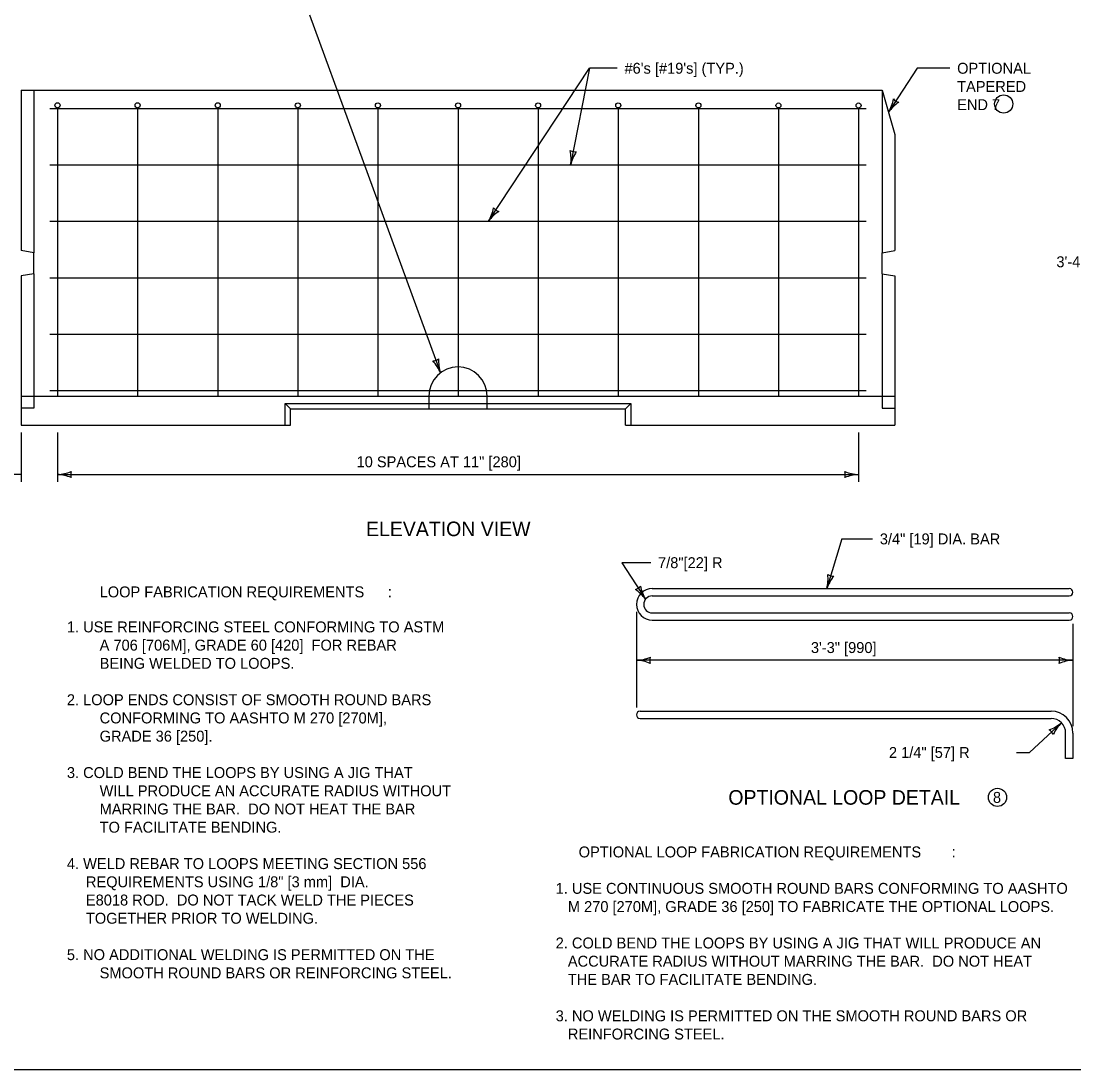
# Model space of a CAD drawing. Extents: x 49991.4 to 50021, y 49987.6 to 50011.4.
# Drawn here: x 50003.08 to 50008.86, y 49987.8 to 49993.56 of the extents above; entities that cross this region are included whole.
import ezdxf

# ---------------------------------------------------------------- set-up
doc = ezdxf.new("R2010")
doc.units = 0
for name, color, linetype in [('Level 1', 7, 'Continuous'), ('Level 2', 7, 'Continuous'), ('Level 3', 7, 'Continuous'), ('Level 4', 7, 'Continuous')]:
    doc.layers.add(name, color=color, linetype=linetype)

msp = doc.modelspace()

# ---------------------------------------------------------------- linework, layer by layer
at = {"layer": 'Level 1'}
for p, q in [((50003.0765, 49993.1796), (50007.8063, 49993.1796)), ((50003.0765, 49993.1796), (50003.0766, 49992.2998)), ((50007.8063, 49993.1796), (50007.8765, 49992.9369)), ((50003.2341, 49993.0799), (50007.7191, 49993.0799)), ((50003.2766, 49993.0817), (50003.2766, 49991.4996)), ((50003.7166, 49993.0817), (50003.7166, 49991.4996)), ((50004.1566, 49993.0817), (50004.1566, 49991.4996)), ((50004.5966, 49993.0817), (50004.5966, 49991.4996)), ((50005.0366, 49993.0817), (50005.0366, 49991.4996)), ((50005.4766, 49993.0817), (50005.4766, 49991.4996)), ((50005.9166, 49993.0817), (50005.9166, 49991.4996)), ((50006.3566, 49993.0817), (50006.3566, 49991.4996)), ((50006.7966, 49993.0817), (50006.7966, 49991.4996)), ((50007.2366, 49993.0817), (50007.2366, 49991.4996)), ((50007.6766, 49993.0817), (50007.6766, 49991.4996)), ((50007.8765, 49992.9369), (50007.8765, 49992.2998)), ((50003.2341, 49992.7699), (50007.7191, 49992.7699)), ((50003.2341, 49992.4599), (50007.7191, 49992.4599)), ((50003.1468, 49992.2862), (50003.0766, 49992.2998)), ((50003.1467, 49992.1703), (50003.1468, 49992.2862)), ((50007.8063, 49992.2862), (50007.8765, 49992.2998)), ((50007.8063, 49992.1703), (50007.8063, 49992.2862)), ((50003.1467, 49992.1703), (50003.0766, 49992.1598)), ((50007.8063, 49992.1703), (50007.8765, 49992.1598)), ((50003.0766, 49992.1598), (50003.0766, 49991.3396)), ((50003.2341, 49992.1499), (50007.7191, 49992.1499)), ((50007.8765, 49992.1598), (50007.8765, 49991.3396)), ((50003.2341, 49991.8399), (50007.7191, 49991.8399)), ((50003.2341, 49991.5299), (50007.7191, 49991.5299)), ((50005.3166, 49991.4996), (50005.3166, 49991.4297)), ((50005.6366, 49991.4297), (50005.6366, 49991.4996)), ((50004.5265, 49991.4596), (50004.5566, 49991.4296)), ((50004.5265, 49991.3396), (50004.5265, 49991.4596)), ((50004.5265, 49991.4596), (50006.4266, 49991.4596)), ((50004.5566, 49991.4296), (50006.3966, 49991.4297)), ((50004.5566, 49991.3396), (50004.5566, 49991.4296)), ((50006.4266, 49991.4596), (50006.3966, 49991.4297)), ((50006.3966, 49991.3396), (50006.3966, 49991.4297)), ((50006.4266, 49991.4596), (50006.4266, 49991.3396)), ((50003.0766, 49991.3396), (50004.5566, 49991.3396)), ((50006.3966, 49991.3396), (50007.8765, 49991.3396)), ((50006.5434, 49990.4422), (50008.834, 49990.4422)), ((50006.5434, 49990.4021), (50008.834, 49990.4021)), ((50006.5434, 49990.3091), (50008.834, 49990.3091)), ((50006.5434, 49990.269), (50008.834, 49990.269)), ((50006.4762, 49989.7691), (50008.7339, 49989.7691)), ((50006.4762, 49989.729), (50008.7339, 49989.729)), ((50008.8139, 49989.5091), (50008.8139, 49989.649)), ((50008.8541, 49989.649), (50008.8541, 49989.5091)), ((50008.8541, 49989.5091), (50008.8139, 49989.5091))]:
    msp.add_line(p, q, dxfattribs=at)
msp.add_lwpolyline([(49999.3835, 49998.9992), (50016.7501, 49998.9992), (50016.7501, 49987.7988), (49999.3835, 49987.7988)], close=True, dxfattribs=at)
for centre, radius, start, end in [((50005.4766, 49991.4996), 0.16, 0, 180), ((50006.5434, 49990.3556), 0.0866, 90, 270), ((50008.834, 49990.4221), 0.02, 270, 90), ((50006.5434, 49990.3556), 0.0465, 90, 270), ((50008.834, 49990.2891), 0.0201, 270, 90), ((50006.4768, 49989.749), 0.02, 91.80967, 268.19034), ((50008.7331, 49989.6481), 0.121, 0.43427, 89.60389), ((50008.7339, 49989.649), 0.08, 360, 90)]:
    msp.add_arc(centre, radius, start, end, dxfattribs=at)
for centre in [(50003.2766, 49993.0967), (50003.7166, 49993.0966), (50004.1566, 49993.0965), (50004.5966, 49993.0964), (50005.0366, 49993.0963), (50005.4766, 49993.0961), (50005.4766, 49993.0961), (50005.9166, 49993.096), (50006.3566, 49993.0959), (50006.7966, 49993.0958), (50007.2366, 49993.0957), (50007.6766, 49993.0956)]:
    msp.add_ellipse(centre, major_axis=(0.0139, 0), ratio=0.997575, dxfattribs=at)
at = {"layer": 'Level 2'}
for centre in [(50008.4739, 49993.1038), (50008.4396, 49989.2956)]:
    msp.add_circle(centre, 0.05, dxfattribs=at)
at = {"layer": 'Level 3'}
for p, q in [((50004.6608, 49993.5928), (50005.3799, 49991.6271)), ((50005.6442, 49992.4599), (50006.1984, 49993.3)), ((50006.1984, 49993.3), (50006.0952, 49992.7699)), ((50006.3509, 49993.3), (50006.1984, 49993.3)), ((50007.9983, 49993.3), (50007.8414, 49993.0586)), ((50008.178, 49993.3), (50007.9983, 49993.3)), ((50003.0765, 49991.2997), (50003.0765, 49991.0287)), ((50003.2766, 49991.2997), (50003.2766, 49991.0287)), ((50007.6766, 49991.2997), (50007.6766, 49991.0287)), ((50003.0765, 49991.0687), (50002.9318, 49991.0687)), ((50003.2766, 49991.0687), (50007.6766, 49991.0687)), ((50007.5841, 49990.7152), (50007.5021, 49990.4422)), ((50007.5841, 49990.7152), (50007.7533, 49990.7152)), ((50006.5353, 49990.5846), (50006.3759, 49990.5846)), ((50006.3759, 49990.5846), (50006.5061, 49990.3834)), ((50006.4568, 49990.3156), (50006.4568, 49989.789)), ((50008.8541, 49990.2491), (50008.8541, 49989.6871)), ((50008.8541, 49990.0485), (50006.4568, 49990.0485)), ((50008.6153, 49989.5422), (50008.7907, 49989.7053)), ((50008.544, 49989.5422), (50008.6153, 49989.5422))]:
    msp.add_line(p, q, dxfattribs=at)
for centre, radius, start, end in [((50007.64, 49993.1758), 0.233, 329.80504, 349.05489), ((50008.0226, 49992.9298), 0.2223, 124.43374, 144.61724), ((50007.9112, 49993.1661), 0.0548, 219.11654, 254.8389), ((50006.1197, 49992.8958), 0.0548, 241.11936, 276.84172), ((50005.8646, 49992.8031), 0.233, 351.80785, 11.0577), ((50006.3115, 49992.7185), 0.2223, 146.43655, 166.62006), ((50005.4436, 49992.5785), 0.233, 329.41633, 348.66618), ((50005.8246, 49992.33), 0.2223, 124.04503, 144.22854), ((50005.7148, 49992.5669), 0.0548, 218.72784, 254.4502), ((50005.3359, 49991.7475), 0.0548, 272.23301, 307.95537), ((50005.5917, 49991.6949), 0.2223, 177.5502, 197.73371), ((50005.1653, 49991.5364), 0.233, 22.9215, 42.17135), ((50003.2651, 49991.3015), 0.233, 272.82731, 292.07716), ((50003.2674, 49990.8466), 0.2223, 67.45601, 87.63952), ((50003.4048, 49991.0687), 0.0548, 162.13882, 197.86118), ((50007.6858, 49991.2909), 0.2223, 247.45601, 267.63952), ((50007.5484, 49991.0687), 0.0548, 342.13882, 17.86118), ((50007.6881, 49990.836), 0.233, 92.82731, 112.07716), ((50007.2759, 49990.4981), 0.233, 346.12301, 5.37286), ((50007.7122, 49990.3696), 0.2223, 140.75171, 160.93521), ((50007.539, 49990.565), 0.0548, 235.43451, 271.15688), ((50006.4364, 49990.491), 0.0548, 285.05282, 320.77518), ((50006.317, 49990.2473), 0.233, 35.74131, 54.99116), ((50006.6976, 49990.4964), 0.2223, 190.37001, 210.55352), ((50006.4453, 49990.2812), 0.233, 272.82731, 292.07716), ((50006.4476, 49989.8264), 0.2223, 67.45601, 87.63952), ((50006.585, 49990.0485), 0.0548, 162.13882, 197.86118), ((50008.8633, 49990.2707), 0.2223, 247.45601, 267.63952), ((50008.7259, 49990.0485), 0.0548, 342.13882, 17.86118), ((50008.8656, 49989.8158), 0.233, 92.82731, 112.07716), ((50008.6462, 49989.8742), 0.2223, 290.37001, 310.55352), ((50008.9576, 49989.5427), 0.233, 135.74131, 154.99116), ((50008.6968, 49989.618), 0.0548, 25.05282, 60.77518)]:
    msp.add_arc(centre, radius, start, end, dxfattribs=at)
at = {"layer": 'Level 4'}
for p, q in [((50003.1468, 49993.1796), (50003.1468, 49992.2862)), ((50007.8063, 49993.1796), (50007.8063, 49992.2862)), ((50003.1467, 49992.1703), (50003.1467, 49991.4332)), ((50007.8063, 49992.1703), (50007.8063, 49991.4332)), ((50003.0766, 49991.4996), (50007.8765, 49991.4996)), ((50003.1467, 49991.4332), (50003.0766, 49991.4332)), ((50007.8063, 49991.4332), (50007.8765, 49991.4332))]:
    msp.add_line(p, q, dxfattribs=at)

# ---------------------------------------------------------------- texts
at = {"layer": 'Level 2'}
for s, height, p in [("#6's [#19's] (TYP.)", 0.06, (50006.3909, 49993.2701)), ('OPTIONAL', 0.06, (50008.218, 49993.27)), ('TAPERED', 0.06, (50008.218, 49993.17)), ('END 7', 0.06, (50008.218, 49993.07)), ('3\'-4 3/4"', 0.06, (50008.7632, 49992.2073)), ('10 SPACES AT 11" [280]', 0.06, (50004.9193, 49991.1087)), ('ELEVATION VIEW', 0.08, (50004.9713, 49990.7303)), ('3/4" [19] DIA. BAR', 0.06, (50007.7933, 49990.6852)), ('7/8"[22] R', 0.06, (50006.5753, 49990.5546)), ('LOOP FABRICATION REQUIREMENTS', 0.06, (50003.5082, 49990.3942)), (':', 0.06, (50005.0909, 49990.3942)), ('1. USE REINFORCING STEEL CONFORMING TO ASTM', 0.06, (50003.3282, 49990.2019)), ('A 706 [706M], GRADE 60 [420]  FOR REBAR ', 0.06, (50003.5082, 49990.1019)), ('3\'-3" [990]', 0.06, (50007.4148, 49990.0885)), ('BEING WELDED TO LOOPS.', 0.06, (50003.5082, 49990.0019)), ('2. LOOP ENDS CONSIST OF SMOOTH ROUND BARS', 0.06, (50003.3282, 49989.8019)), ('CONFORMING TO AASHTO M 270 [270M], ', 0.06, (50003.5082, 49989.7019)), ('GRADE 36 [250].', 0.06, (50003.5082, 49989.6019)), ('2 1/4" [57] R', 0.06, (50007.8434, 49989.5122)), ('3. COLD BEND THE LOOPS BY USING A JIG THAT', 0.06, (50003.3282, 49989.4019)), ('WILL PRODUCE AN ACCURATE RADIUS WITHOUT', 0.06, (50003.5082, 49989.3019)), ('OPTIONAL LOOP DETAIL', 0.08, (50006.9614, 49989.2556)), ('8', 0.06, (50008.4146, 49989.2656)), ('MARRING THE BAR.  DO NOT HEAT THE BAR', 0.06, (50003.5082, 49989.2019)), ('TO FACILITATE BENDING.', 0.06, (50003.5082, 49989.1019)), ('OPTIONAL LOOP FABRICATION REQUIREMENTS', 0.06, (50006.1392, 49988.966)), (':', 0.06, (50008.1875, 49988.966)), ('4. WELD REBAR TO LOOPS MEETING SECTION 556 ', 0.06, (50003.3282, 49988.9019)), ('  REQUIREMENTS USING 1/8" [3 mm]  DIA. ', 0.06, (50003.3882, 49988.8019)), ('1. USE CONTINUOUS SMOOTH ROUND BARS CONFORMING TO AASHTO ', 0.06, (50006.013, 49988.766)), ('  E8018 ROD.  DO NOT TACK WELD THE PIECES ', 0.06, (50003.3882, 49988.7019)), ('   M 270 [270M], GRADE 36 [250] TO FABRICATE THE OPTIONAL LOOPS.   ', 0.06, (50006.013, 49988.666)), ('  TOGETHER PRIOR TO WELDING.', 0.06, (50003.3882, 49988.6019)), ('2. COLD BEND THE LOOPS BY USING A JIG THAT WILL PRODUCE AN ', 0.06, (50006.013, 49988.466)), ('5. NO ADDITIONAL WELDING IS PERMITTED ON THE', 0.06, (50003.3282, 49988.4019)), ('   ACCURATE RADIUS WITHOUT MARRING THE BAR.  DO NOT HEAT ', 0.06, (50006.013, 49988.366)), ('SMOOTH ROUND BARS OR REINFORCING STEEL.', 0.06, (50003.5082, 49988.3019)), ('   THE BAR TO FACILITATE BENDING.', 0.06, (50006.013, 49988.266)), ('3. NO WELDING IS PERMITTED ON THE SMOOTH ROUND BARS OR ', 0.06, (50006.013, 49988.066)), ('   REINFORCING STEEL.', 0.06, (50006.013, 49987.966))]:
    msp.add_text(s, height=height, dxfattribs=at).set_placement(p)

doc.saveas('drawing.dxf')
